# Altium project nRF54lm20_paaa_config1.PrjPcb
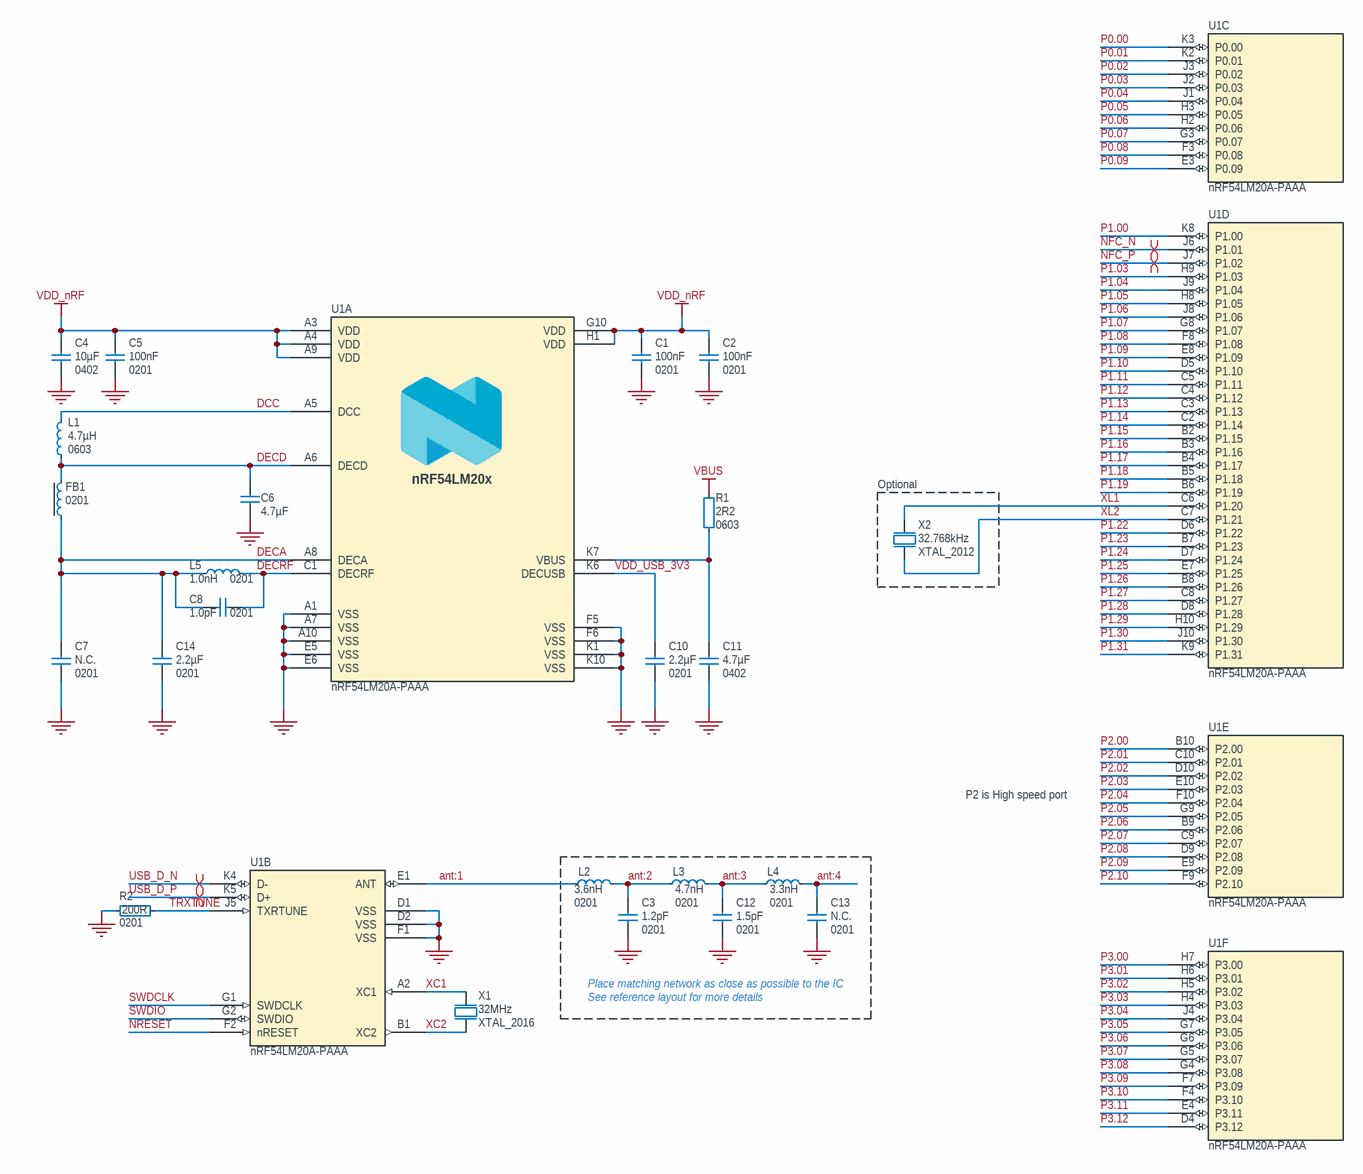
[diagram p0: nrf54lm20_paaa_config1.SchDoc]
Classification: Confidential; Designer: =DrawnBy; Device: nRF54LM20-CAAA; DrawnBy: GETR; PCAName: nRF54LM20 Reference Layout; PCARevision: =Revision; ProjectTitle: =Title; RefLayoutTitle: =Title; Revision: v0.1.0; Title: nRF54LM20-caaa Reference Layout
1 sheet, 24 parts. Net scope: global (net labels, ports and power ports of the same name join across sheets).
Board file: nrf54lm20_paaa_config1.PcbDoc

## Sheet nrf54lm20_paaa_config1.SchDoc: nRF54LM20-caaa Reference Layout
size A3; SheetNumber: 1; SheetTotal: 1

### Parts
C1  100nF  Footprint Doc: 0201  [CAPC0603X03L_C]
C2  100nF  Footprint Doc: 0201  [CAPC0603X03L_C]
C3  1.2pF  Footprint Doc: 0201  [CAPC0603X03L_C]
C4  10µF  Footprint Doc: 0402  [CAPC1005X04L]
C5  100nF  Footprint Doc: 0201  [CAPC0603X03L_C]
C6  4.7µF  [CAPC0603X03L_C]
C7  N.C.  Footprint Doc: 0201  [CAPC0603X03L_C_NC]
C8  1.0pF  Footprint Doc: 0201  [CAPC0603X03L_C]
C10  2.2µF  Footprint Doc: 0201  [CAPC0603X03L_C]
C11  4.7µF  Footprint Doc: 0402  [CAPC1005X04L]
C12  1.5pF  Footprint Doc: 0201  [CAPC0603X03L_C]
C13  N.C.  Footprint Doc: 0201  [CAPC0603X03L_C_NC]
C14  2.2µF  Footprint Doc: 0201  [CAPC0603X03L_C]
FB1  Footprint Doc: 0201  [INDC0603X03L_C]  (hidden comment: 120R/0.2A)
L1  4.7µH  Footprint Doc: 0603  [INDC1608X06L]
L2  3.6nH  Footprint Doc: 0201  [INDC0603X03L_C]
L3  4.7nH  Footprint Doc: 0201  [INDC0603X03L_C]
L4  3.3nH  Footprint Doc: 0201  [INDC0603X03L_C]
L5  1.0nH  Footprint Doc: 0201  [INDC0603X03L_C]
R1  2R2  Footprint Doc: 0603  [RESC1608X06L]
R2  200R  Footprint Doc: 0201  [RESC0603X03L_C]
U1  nRF54LM20A-PAAA  [BGA98C35P10X10_367X385X86]  (parts A,B,C,D,E,F of 6)
X1  32MHz  Footprint Doc: XTAL_2016  [BT-XTAL_2016]
X2  32.768kHz  [XTAL_2012]

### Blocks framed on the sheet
Optional: X2

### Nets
GND: C1.2 C2.2 C3.1 C4.1 C5.2 C6.1 C7.2 C10.1 C11.1 C12.2 C13.1 C14.1 R2.1 U1.A1(VSS) U1.A7(VSS) U1.A10(VSS) U1.D1(VSS) U1.D2(VSS) U1.E5(VSS) U1.E6(VSS) U1.F1(VSS) U1.F5(VSS) U1.F6(VSS) U1.K1(VSS) U1.K10(VSS) X1.2(GND) X1.4(GND)
VBUS: R1.2
VDD_nRF: C1.1 C2.1 C4.2 C5.1 U1.A3(VDD) U1.A4(VDD) U1.A9(VDD) U1.G10(VDD) U1.H1(VDD)
ant:1: L2.1 U1.E1(ANT)
ant:2: C3.2 L2.2 L3.1
ant:3: C12.1 L3.2 L4.1
ant:4: C13.2 L4.2
DCC: L1.1 U1.A5(DCC)
DECA: C7.1 C8.2 C14.2 FB1.2 L5.1 U1.A8(DECA)
DECD: C6.2 FB1.1 L1.2 U1.A6(DECD)
DECRF: C8.1 L5.2 U1.C1(DECRF)
NFC_N: U1.J6(P1.01)
NFC_P: U1.J7(P1.02)
NRESET: U1.F2(nRESET)
P0.00: U1.K3(P0.00)
P0.01: U1.K2(P0.01)
P0.02: U1.J3(P0.02)
P0.03: U1.J2(P0.03)
P0.04: U1.J1(P0.04)
P0.05: U1.H3(P0.05)
P0.06: U1.H2(P0.06)
P0.07: U1.G3(P0.07)
P0.08: U1.F3(P0.08)
P0.09: U1.E3(P0.09)
P1.00: U1.K8(P1.00)
P1.03: U1.H9(P1.03)
P1.04: U1.J9(P1.04)
P1.05: U1.H8(P1.05)
P1.06: U1.J8(P1.06)
P1.07: U1.G8(P1.07)
P1.08: U1.F8(P1.08)
P1.09: U1.E8(P1.09)
P1.10: U1.D5(P1.10)
P1.11: U1.C5(P1.11)
P1.12: U1.C4(P1.12)
P1.13: U1.C3(P1.13)
P1.14: U1.C2(P1.14)
P1.15: U1.B2(P1.15)
P1.16: U1.B3(P1.16)
P1.17: U1.B4(P1.17)
P1.18: U1.B5(P1.18)
P1.19: U1.B6(P1.19)
P1.22: U1.D6(P1.22)
P1.23: U1.B7(P1.23)
P1.24: U1.D7(P1.24)
P1.25: U1.E7(P1.25)
P1.26: U1.B8(P1.26)
P1.27: U1.C8(P1.27)
P1.28: U1.D8(P1.28)
P1.29: U1.H10(P1.29)
P1.30: U1.J10(P1.30)
P1.31: U1.K9(P1.31)
P2.00: U1.B10(P2.00)
P2.01: U1.C10(P2.01)
P2.02: U1.D10(P2.02)
P2.03: U1.E10(P2.03)
P2.04: U1.F10(P2.04)
P2.05: U1.G9(P2.05)
P2.06: U1.B9(P2.06)
P2.07: U1.C9(P2.07)
P2.08: U1.D9(P2.08)
P2.09: U1.E9(P2.09)
P2.10: U1.F9(P2.10)
P3.00: U1.H7(P3.00)
P3.01: U1.H6(P3.01)
P3.02: U1.H5(P3.02)
P3.03: U1.H4(P3.03)
P3.04: U1.J4(P3.04)
P3.05: U1.G7(P3.05)
P3.06: U1.G6(P3.06)
P3.07: U1.G5(P3.07)
P3.08: U1.G4(P3.08)
P3.09: U1.F7(P3.09)
P3.10: U1.F4(P3.10)
P3.11: U1.E4(P3.11)
P3.12: U1.D4(P3.12)
SWDCLK: U1.G1(SWDCLK)
SWDIO: U1.G2(SWDIO)
TRXTUNE: R2.2 U1.J5(TXRTUNE)
USB_D_N: U1.K4(D-)
USB_D_P: U1.K5(D+)
VDD_USB_3V3: C10.2 U1.K6(DECUSB)
XC1: U1.A2(XC1) X1.1(inp)
XC2: U1.B1(XC2) X1.3(out)
XL1: U1.C6(P1.20) X2.2(out)
XL2: U1.C7(P1.21) X2.1(inp)
NetC11_2: C11.2 R1.1 U1.K7(VBUS)

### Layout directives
differential pair; differential pair class USB: USB_D_N, USB_D_P
differential pair; differential pair class NFC: NFC_N, NFC_P

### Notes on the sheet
- P2 is High speed port
- See reference layout for more details
- Place matching network as close as possible to the IC

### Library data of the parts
C1 C2 C5 = C0201-100n-10V-X7R: Capacitor, X7R, ±10%; Manufacturer: N.A.; Part number NEMS: 100200469; Note: 10V; Pad Count: 2; Component Status: Active
C3 = C0201-1.2p-HQ-Murata: Capacitor, NP0, ±0.05pF, 50V; Manufacturer: Murata; Manufacturer Part Number: GJM0335C1H1R2WB01D; Part number NEMS: 100200457; Component Status: Active; Pad Count: 2; Artikkelnr Noca: N.A.
C4 = C0402-10µF-6.3V-X6S: Capacitor, X6S, ±20%, 6.3V; Manufacturer: N.A.; Part number NEMS: 100200478; Component Status: Active; Pad Count: 2
C6 = C0201-4.7µ-6V3-X5R-GRM035R60J475ME15J: Capacitor, Ceramic, X5R, ±20%, 6.3V; Manufacturer: Murata; Part number NEMS: 100200685; Component Status: Active; Pad Count: 2; Note: -55°C ~ 85°C; Artikkelnr Noca: N.A.
C7 C13 = C0201-N.C.: Not mounted; Manufacturer: N.A.; Part number NEMS: 100200001; Component Status: Active; Pad Count: 2; Note: Chip Cap; Assembly: Not mounted
C8 = C0201-1p0-25V-COG-GJM0335C1E1R0WB01: CAP CER 1.0PF 25V C0G/NP0 0201; Manufacturer: Murata; Part number NEMS: 100200676; Component Status: Active; Pad Count: 2; Artikkelnr Noca: N.A.
C10 = C0201-2µ2-2.5V-X6T-GRM033D80E225ME47D: Capacitor, Ceramic, 2.2µF 2.5V X6T 0201,±20%; Manufacturer: Murata; Manufacturer Part Number: GRM033R61A225KE47; Part number NEMS: 100200527; Component Status: Active; Pad Count: 2; Note: 2.5V, 20%, X6T; Artikkelnr Noca: N.A.
C11 = C0402-4µ7-10V-X5R: Capacitor, X5R, 10V; Manufacturer: Murata; Manufacturer Part Number: GRM155R61A475MEAAD; Part number NEMS: 100200415; Component Status: Active; Pad Count: 2; Artikkelnr Noca: N.A.
C12 = C0201-1.5p-25V-NP0-GJM0335C1E1R5WB01: Capacitor, NP0, ±0.05pF, 25V, High Q; Manufacturer: Murata; Part number NEMS: 100200477; Component Status: Active; Pad Count: 2; Artikkelnr Noca: N.A.
C14 = C0201-2µ2-2.5V-X6T-GRM033D80E225ME47D: Capacitor, Ceramic, 2.2µF 2.5V X6T 0201,±20%; Manufacturer: Murata; Part number NEMS: 100200527; Component Status: Active; Pad Count: 2; Note: 2.5V, 20%, X6T; Artikkelnr Noca: N.A.
FB1 = FB0201-120R@100M-200mA-BLM03AG121SN1D: Ferrite Bead, 120 Ohm @ 100MHz, 200mA, 500 mOhm Max; Manufacturer: Murata; Part number NEMS: 100300419; Component Status: Active; Pad Count: 2; Artikkelnr Noca: N.A.
L1 = L0603-4µ7-MLZ1608M4R7WT000: Inductor, 120mA, ±20%, 0.65R; Manufacturer: TDK Corporation; Part number NEMS: 100300440; Component Status: Active; Pad Count: 2; Note: Power Inductor ±20%; Artikkelnr Noca: N.A.
L2 = L0201-3n6-HQ-Murata: Inductor, 500mA, ±0.1ｎH, 170mOhm; Manufacturer: Murata; Manufacturer Part Number: LQP03HQ3N6B02; Part number NEMS: 100300223; Component Status: Active; Pad Count: 2; Note: -55°C ~ 125°C; Artikkelnr Noca: N.A.
L3 = L0201-4n7-HQ-Murata: Inductor, 400mA, ±3%, 250mOhm; Manufacturer: Murata; Manufacturer Part Number: LQP03HQ4N7H02; Part number NEMS: 100300231; Component Status: Active; Pad Count: 2; Note: -55°C ~ 125°C; Artikkelnr Noca: N.A.
L4 = L0201-3n3-HQ-Murata: Inductor, 500mA, ±0.1ｎH, 170mOhm; Manufacturer: Murata; Manufacturer Part Number: LQP03HQ3N3B02; Part number NEMS: 100300220; Component Status: Active; Pad Count: 2; Note: -55°C ~ 125°C; Artikkelnr Noca: N.A.
L5 = L0201-1n0: Inductor, 750mA, ±0.2nH; Manufacturer: Murata; Manufacturer Part Number: LQP03TN1N0C02D; Part number NEMS: 100300012; Component Status: Active; Pad Count: 2; Note: High frequency chip inductor ±5%; Artikkelnr Noca: N.A.
R1 = R0603-2R2: RES 2.2 OHM 1% 1/10W 0603; Manufacturer: N.A.; Component Status: Active; Pad Count: 2; Note: Chip Res 1%
R2 = R0201-200: Resistor, ±1%, 0.05W; Manufacturer: N.A.; Part number NEMS: 100100611; Component Status: Active; Pad Count: 2; Note: Chip Res 1%
U1 = nRF54LM20A-PAAA: nRF54 series BLE; Manufacturer: Nordic Semiconductor; Component Status: Active; Pad Count: 98; Note: N.A.
X1 = XTAL_SMD2016_32MHz_8pF_Kyocera: XTAL SMD 2016, 32MHz, Cl=8pF, Tot: ±40ppm; Manufacturer Part Number: CX2016DB32000D0WZRC1; Part number IPS: 00000007827; Part number Norautron: 26511136; Part number NEMS: 101600039; Component Status: Active; Pad Count: 4; Note: XTAL SMD 32.000MHz; Artikkelnr Noca: 22010022
X2 = XTAL_SMD2012_32.768kHz_9pF_TXC: XTAL SMD 2012, 32.768kHz, 9pF, ±20ppm; Manufacturer: TXC Corporation; Manufacturer Part Number: 9HT11-32.768KDZC-T; Part number NEMS: 101600107; Component Status: Active; Pad Count: 2; Note: XTAL SMD 32.768kHz; Artikkelnr Noca: N.A.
